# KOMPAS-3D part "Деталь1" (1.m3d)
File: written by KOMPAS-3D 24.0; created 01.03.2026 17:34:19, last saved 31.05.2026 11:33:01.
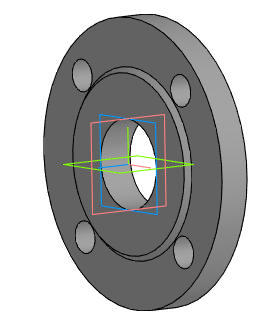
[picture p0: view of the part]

Document properties: Автор: R2D2; Полное имя файла: E:\Работа\Зайцев\GVWR3131M-2W-F-S Задвижка клиновая 30нж64нж DN.ru  Ду50-150 Ру25\исходные данные\DN50\1.m3d

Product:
- Part/product: Деталь1
    Масса: 2.437209
    additional columns: Типовые
- Part/product: Деталь1  | designation Деталь1-01
    Масса: 2.437209
    additional columns: Типовые

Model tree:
1. Эскиз:2
2. Элемент вращения:1
     Угол 1 = 360
3. Эскиз:3  (with: Грань.Элемент вращения:1)
4. Элемент выдавливания:2
     Расстояние 2 = 17
5. Массив по концентрической сетке:1  (with: Элемент выдавливания:2, Эскиз:3, Грань.Элемент вращения:1)  (4 pattern instances)
     Шаг 2 = 360

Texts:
  Деталь1-01
  Линейный размер с обрывом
